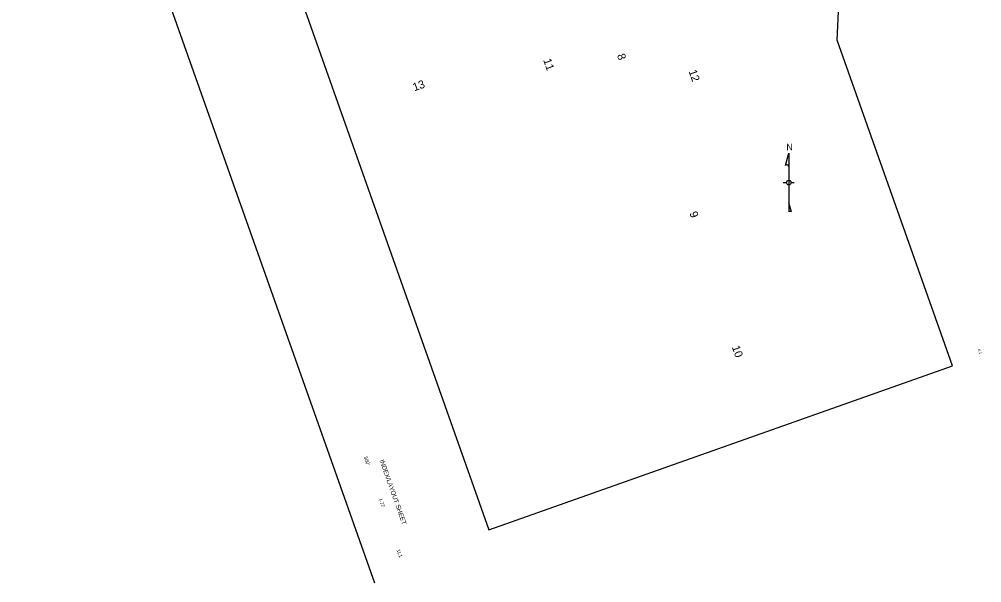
# Model space of a CAD drawing. Extents: x 2000223 to 2009769, y 1132098 to 1143273.
# Drawn here: x 2000223 to 2009769, y 1132098 to 1137686 of the extents above; entities that cross this region are included whole.
import ezdxf

# ---------------------------------------------------------------- set-up
doc = ezdxf.new("R2010")
doc.units = 0
for name, color, linetype in [('North Arrow', 7, 'Continuous'), ('RD_SHT_ShtClip', 7, 'Continuous'), ('RD_SHT_TX', 7, 'Continuous')]:
    doc.layers.add(name, color=color, linetype=linetype)

msp = doc.modelspace()

# ---------------------------------------------------------------- linework, layer by layer
at = {"layer": 'North Arrow'}
for p, q in [((2007822, 1136236.6), (2007855.5, 1136356.1)), ((2007855.5, 1136356.1), (2007855.5, 1136230.3)), ((2007855.5, 1136356.1), (2007855.5, 1135776.1)), ((2007800.4, 1136066.1), (2007832.7, 1136066.1)), ((2007878.3, 1136066.1), (2007910.5, 1136066.1)), ((2007855.5, 1135865.9), (2007855.5, 1135776.1)), ((2007881.3, 1135774.7), (2007855.5, 1135865.9))]:
    msp.add_line(p, q, dxfattribs=at)
msp.add_circle((2007855.5, 1136066.1), 22.8, dxfattribs=at)
for centre, radius, start, end in [((2007836.7, 1136222.5), 20.3, 22.37065, 136.13874), ((2007867.7, 1135761.8), 18.7, 43.33968, 130.56069)]:
    msp.add_arc(centre, radius, start, end, dxfattribs=at)
at = {"layer": 'RD_SHT_ShtClip'}
msp.add_lwpolyline([(2008381.9, 1138477.9), (2005909, 1139418.3), (2005354.6, 1141003.5), (2002299.7, 1139921.3), (2004881.5, 1132623.3), (2009479.3, 1134249.9), (2008336.7, 1137479.8)], close=True, dxfattribs=at)
at = {"layer": 'RD_SHT_TX'}
msp.add_line((2000223, 1142053.2), (2003744.9, 1132097.8), dxfattribs=at)

# ---------------------------------------------------------------- texts
at = {"layer": 'North Arrow'}
msp.add_text('N', height=63.2, dxfattribs=at).set_placement((2007832.3, 1136387.2))
at = {"layer": 'RD_SHT_TX'}
for s, height, rotation, p in [('11', 80, 289.48201, (2005418.7, 1137280.6)), ('8', 80, 289.48201, (2006150.3, 1137328.5)), ('12', 80, 289.48201, (2006861.2, 1137170.2)), ('13', 80, 19.48201, (2004141.5, 1136971.1)), ('9', 80, 289.48201, (2006868.7, 1135764.4)), ('10', 80, 289.48201, (2007289.6, 1134435.4)), ('IL1', 27, 289.48201, (2009729.8, 1134411.9)), ("300'", 36, 289.48201, (2003637.4, 1133346.1)), ('INDEX/LAYOUT SHEET', 45, 289.48201, (2003796.1, 1133310.1)), ('I-77', 36, 289.48201, (2003787.2, 1132922.8)), ('1L1', 36, 289.48201, (2003964.1, 1132422.7))]:
    msp.add_text(s, height=height, rotation=rotation, dxfattribs=at).set_placement(p)

doc.saveas('drawing.dxf')
